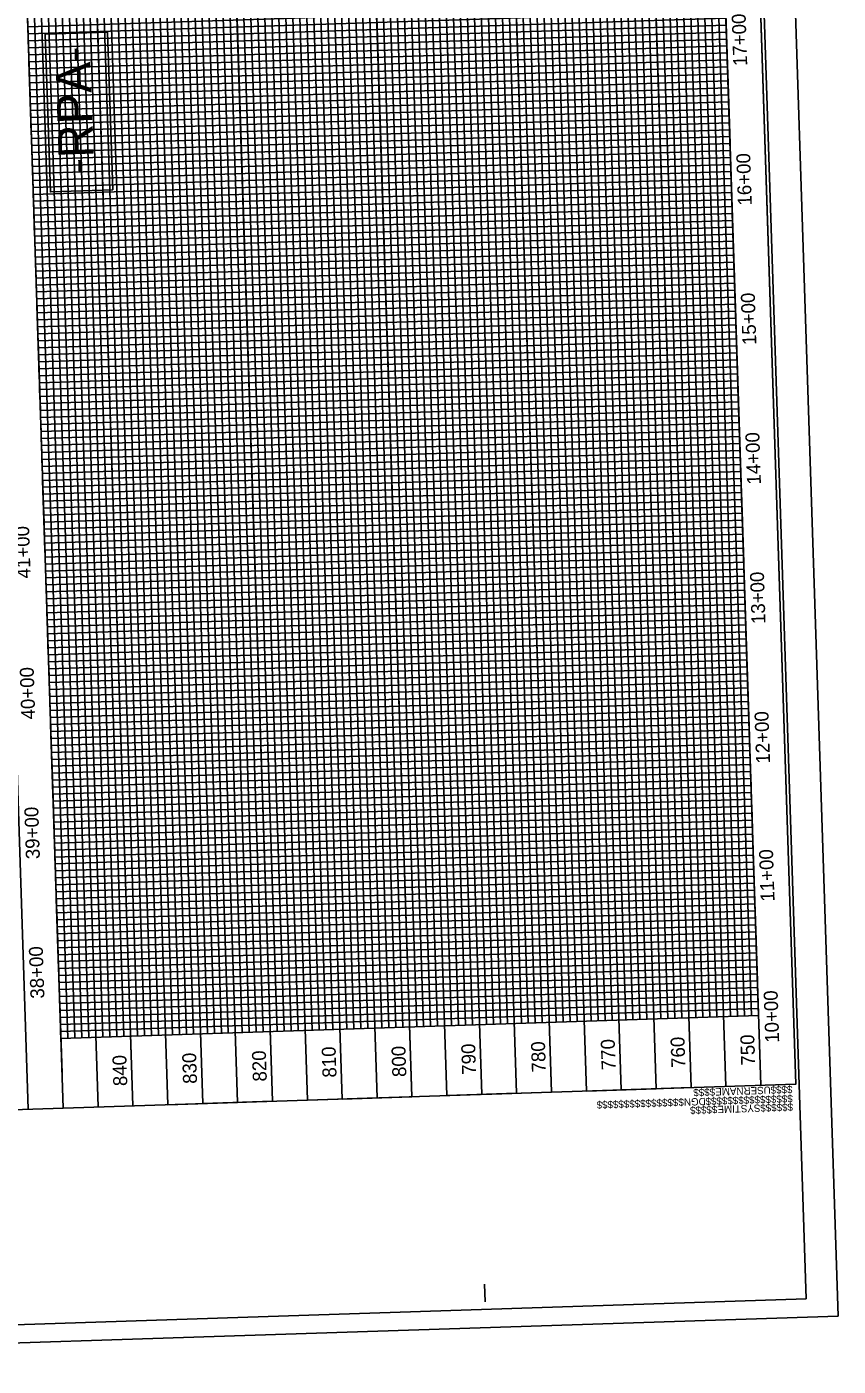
# Model space of a CAD drawing. Extents: x 1627318 to 1628473, y 762308 to 764226.
# Drawn here: x 1627891 to 1628473, y 762308 to 763268 of the extents above; entities that cross this region are included whole.
import ezdxf

# ---------------------------------------------------------------- set-up
doc = ezdxf.new("R2010")
doc.units = 0
for name, color, linetype in [('Exist Vertical Profile Horizontal Axis Label Major', 7, 'Continuous'), ('Exist Vertical Profile Vertical Axis Label', 7, 'Continuous'), ('Prop Grid Mask', 7, 'Continuous'), ('Sheet Data Field CELL', 7, 'Continuous'), ('Sheet DOT Grid CELL', 7, 'Continuous'), ('Sheet Layout Profile Border Port 2', 7, 'Continuous'), ('Sheet Plot Border Inside CELL', 7, 'Continuous'), ('Sheet Plot Border Outside CELL', 7, 'Continuous'), ('Sheet Profile CELL', 7, 'Continuous'), ('Sheet Profile Grid Major CELL', 7, 'Continuous'), ('Sheet Profile Grid Middle CELL', 7, 'Continuous'), ('Sheet Profile Grid Minor CELL', 7, 'Continuous')]:
    doc.layers.add(name, color=color, linetype=linetype)

msp = doc.modelspace()

# ---------------------------------------------------------------- linework, layer by layer
at = {"layer": 'Prop Grid Mask'}
msp.add_lwpolyline([(1627952.93, 763151.16), (1627949.24, 763264.18), (1627904.52, 763262.72), (1627908.21, 763149.69)], close=True, dxfattribs=at)
at = {"layer": 'Sheet DOT Grid CELL'}
for p, q in [((1628167.24, 762501.5), (1628118.21, 764000.59)), ((1628217.22, 762503.14), (1628168.18, 764002.22)), ((1628267.19, 762504.77), (1628218.15, 764003.86)), ((1628317.16, 762506.41), (1628268.13, 764005.49)), ((1628367.14, 762508.04), (1628318.1, 764007.13)), ((1627917.38, 762493.33), (1627868.34, 763992.41)), ((1627967.35, 762494.96), (1627918.31, 763994.05)), ((1628017.32, 762496.6), (1627968.29, 763995.68)), ((1628067.3, 762498.23), (1628018.26, 763997.32)), ((1628117.27, 762499.87), (1628068.23, 763998.95)), ((1627892.86, 763242.93), (1628392.59, 763259.27)), ((1627894.49, 763192.95), (1628394.22, 763209.3)), ((1627896.13, 763142.98), (1628395.86, 763159.33)), ((1627897.76, 763093.01), (1628397.49, 763109.35)), ((1627899.4, 763043.04), (1628399.13, 763059.38)), ((1627901.03, 762993.06), (1628400.76, 763009.41)), ((1627902.66, 762943.09), (1628402.4, 762959.43)), ((1627904.3, 762893.12), (1628404.03, 762909.46)), ((1627905.93, 762843.14), (1628405.67, 762859.49)), ((1627907.57, 762793.17), (1628407.3, 762809.51)), ((1627909.2, 762743.2), (1628408.94, 762759.54)), ((1627910.84, 762693.22), (1628410.57, 762709.57)), ((1627912.47, 762643.25), (1628412.21, 762659.6)), ((1627914.11, 762593.28), (1628413.84, 762609.62)), ((1627915.74, 762543.3), (1628415.47, 762559.65))]:
    msp.add_line(p, q, dxfattribs=at)
at = {"layer": 'Sheet Layout Profile Border Port 2'}
msp.add_lwpolyline([(1627915.74, 762543.3), (1627869.97, 763942.55), (1628369.71, 763958.9), (1628415.47, 762559.65)], close=True, dxfattribs=at)
at = {"layer": 'Sheet Plot Border Inside CELL'}
msp.add_lwpolyline([(1628449.68, 762356.66), (1628395.2, 764022.27), (1627340.66, 763987.77), (1627395.14, 762322.16)], close=True, dxfattribs=at)
at = {"layer": 'Sheet Plot Border Outside CELL'}
msp.add_lwpolyline([(1628472.54, 762344.4), (1628416.96, 764043.49), (1627317.55, 764007.53), (1627373.13, 762308.44)], close=True, dxfattribs=at)
at = {"layer": 'Sheet Profile CELL'}
for p, q in [((1628442.1, 762510.49), (1628393.06, 764009.69)), ((1628368.07, 764008.87), (1628417.11, 762509.68)), ((1627892.39, 762492.51), (1627843.35, 763991.71)), ((1627917.38, 762493.33), (1627868.34, 763992.53)), ((1628442.1, 762510.49), (1628442.1, 762510.49)), ((1628442.1, 762510.49), (1628442.1, 762510.49)), ((1628442.1, 762510.49), (1628442.1, 762510.49)), ((1628442.1, 762510.49), (1628442.1, 762510.49)), ((1628442.1, 762510.49), (1628442.1, 762510.49)), ((1628442.1, 762510.49), (1628442.1, 762510.49)), ((1628442.1, 762510.49), (1628442.1, 762510.49)), ((1628219.57, 762354.63), (1628219.16, 762367.13))]:
    msp.add_line(p, q, dxfattribs=at)
msp.add_lwpolyline([(1627343.62, 763975.36), (1627392.66, 762476.17), (1628442.1, 762510.49), (1628393.06, 764009.69)], close=True, dxfattribs=at)
msp.add_lwpolyline([(1628440.87, 762547.97), (1628440.87, 762547.97)], dxfattribs=at)
at = {"layer": 'Sheet Profile Grid Major CELL'}
for p, q in [((1627894.49, 763192.95), (1627892.86, 763242.93)), ((1627897.76, 763093.01), (1627896.13, 763142.98)), ((1627901.03, 762993.06), (1627899.4, 763043.04)), ((1628417.11, 762509.68), (1628417.11, 762509.68))]:
    msp.add_line(p, q, dxfattribs=at)
for points in [[(1628068.23, 763999.07), (1628117.27, 762499.87), (1628167.24, 762501.5), (1628118.2, 764000.7)], [(1628168.18, 764002.33), (1628217.22, 762503.14), (1628267.19, 762504.77), (1628218.15, 764003.97)], [(1628268.12, 764005.6), (1628317.16, 762506.41), (1628317.16, 762506.41), (1628367.14, 762508.04), (1628318.1, 764007.24)], [(1628368.07, 764008.87), (1628417.11, 762509.68)], [(1627918.31, 763994.16), (1627967.35, 762494.96)], [(1627968.28, 763995.8), (1628017.32, 762496.6), (1628067.3, 762498.23), (1628018.26, 763997.43)], [(1627915.74, 762543.3), (1628415.47, 762559.65), (1628413.84, 762609.62), (1627914.11, 762593.28), (1627912.47, 762643.25), (1628412.21, 762659.6), (1628410.57, 762709.57), (1627910.84, 762693.22), (1627909.2, 762743.2), (1628408.94, 762759.54), (1628407.3, 762809.51), (1627907.57, 762793.17), (1627905.93, 762843.14), (1628405.67, 762859.49), (1628404.03, 762909.46), (1627904.3, 762893.12), (1627902.66, 762943.09), (1628402.4, 762959.43), (1628400.76, 763009.41), (1627901.03, 762993.06), (1627899.4, 763043.04), (1628399.13, 763059.38), (1628397.49, 763109.35), (1627897.76, 763093.01), (1627896.13, 763142.98), (1628395.86, 763159.33), (1628394.22, 763209.3), (1627894.49, 763192.95), (1627892.86, 763242.93), (1628392.59, 763259.27), (1628390.96, 763309.25)]]:
    msp.add_lwpolyline(points, dxfattribs=at)
at = {"layer": 'Sheet Profile Grid Middle CELL'}
for points in [[(1628043.24, 763998.25), (1628092.28, 762499.05), (1628142.26, 762500.68), (1628093.22, 763999.88)], [(1628143.19, 764001.52), (1628192.23, 762502.32), (1628242.2, 762503.95), (1628193.16, 764003.15)], [(1628243.14, 764004.79), (1628292.18, 762505.59), (1628342.15, 762507.22), (1628293.11, 764006.42)], [(1628343.08, 764008.06), (1628392.12, 762508.86)], [(1627942.36, 762494.15), (1627893.32, 763993.34)], [(1627943.3, 763994.98), (1627992.34, 762495.78), (1628042.31, 762497.42), (1627993.27, 763996.61)], [(1627916.56, 762518.32), (1627914.92, 762568.29), (1628414.66, 762584.64), (1628413.02, 762634.61), (1627913.29, 762618.26), (1627911.66, 762668.24), (1628411.39, 762684.58), (1628409.75, 762734.55), (1627910.02, 762718.21), (1627908.39, 762768.18), (1628408.12, 762784.53), (1628406.48, 762834.5), (1627906.75, 762818.16), (1627905.12, 762868.13), (1628404.85, 762884.47), (1628403.21, 762934.45), (1627903.48, 762918.1), (1627901.85, 762968.08), (1628401.58, 762984.42), (1628399.95, 763034.39), (1627900.21, 763018.05), (1627898.58, 763068.02), (1628398.31, 763084.37), (1628396.68, 763134.34), (1628396.68, 763134.34), (1627896.94, 763117.99), (1627895.31, 763167.97), (1628395.04, 763184.31), (1628393.41, 763234.29), (1627893.67, 763217.94), (1627892.04, 763267.91), (1628391.77, 763284.26)]]:
    msp.add_lwpolyline(points, dxfattribs=at)
at = {"layer": 'Sheet Profile Grid Minor CELL'}
for p, q in [((1628154.82, 763951.87), (1628200.59, 762552.62)), ((1628205.59, 762552.78), (1628159.82, 763952.03)), ((1628164.81, 763952.2), (1628210.58, 762552.95)), ((1628220.58, 762553.27), (1628174.81, 763952.53)), ((1628179.81, 763952.69), (1628225.58, 762553.44)), ((1628230.57, 762553.6), (1628184.8, 763952.85)), ((1628189.8, 763953.02), (1628235.57, 762553.76)), ((1628245.57, 762554.09), (1628199.8, 763953.34)), ((1628204.79, 763953.51), (1628250.56, 762554.25)), ((1628255.56, 762554.42), (1628209.79, 763953.67)), ((1628214.79, 763953.83), (1628260.56, 762554.58)), ((1628270.55, 762554.91), (1628224.78, 763954.16)), ((1628229.78, 763954.32), (1628275.55, 762555.07)), ((1628280.55, 762555.24), (1628234.78, 763954.49)), ((1628239.77, 763954.65), (1628285.54, 762555.4)), ((1628295.54, 762555.73), (1628249.77, 763954.98)), ((1628254.77, 763955.14), (1628300.54, 762555.89)), ((1628305.53, 762556.05), (1628259.76, 763955.3)), ((1628264.76, 763955.47), (1628310.53, 762556.22)), ((1628320.53, 762556.54), (1628274.76, 763955.79)), ((1628279.75, 763955.96), (1628325.52, 762556.71)), ((1628330.52, 762556.87), (1628284.75, 763956.12)), ((1628289.75, 763956.28), (1628335.52, 762557.03)), ((1628345.51, 762557.36), (1628299.74, 763956.61)), ((1628304.74, 763956.78), (1628350.51, 762557.52)), ((1628355.51, 762557.69), (1628309.74, 763956.94)), ((1628314.73, 763957.1), (1628360.5, 762557.85)), ((1628370.5, 762558.18), (1628324.73, 763957.43)), ((1628329.73, 763957.59), (1628375.5, 762558.34)), ((1628380.49, 762558.5), (1628334.72, 763957.76)), ((1628339.72, 763957.92), (1628385.49, 762558.67)), ((1628395.49, 762558.99), (1628349.72, 763958.25)), ((1628354.71, 763958.41), (1628400.48, 762559.16)), ((1628405.48, 762559.32), (1628359.71, 763958.57)), ((1628410.48, 762559.49), (1628364.71, 763958.74)), ((1627920.74, 762543.47), (1627874.97, 763942.72)), ((1627879.97, 763942.88), (1627925.74, 762543.63)), ((1627930.73, 762543.79), (1627884.96, 763943.04)), ((1627889.96, 763943.21), (1627935.73, 762543.96)), ((1627945.73, 762544.28), (1627899.96, 763943.53)), ((1627904.95, 763943.7), (1627950.72, 762544.45)), ((1627955.72, 762544.61), (1627909.95, 763943.86)), ((1627914.95, 763944.03), (1627960.72, 762544.77)), ((1627970.71, 762545.1), (1627924.94, 763944.35)), ((1627929.94, 763944.52), (1627975.71, 762545.26)), ((1627980.71, 762545.43), (1627934.94, 763944.68)), ((1627939.94, 763944.84), (1627985.7, 762545.59)), ((1627995.7, 762545.92), (1627949.93, 763945.17)), ((1627954.93, 763945.33), (1628000.7, 762546.08)), ((1628005.69, 762546.24), (1627959.92, 763945.5)), ((1627964.92, 763945.66), (1628010.69, 762546.41)), ((1628020.69, 762546.74), (1627974.92, 763945.99)), ((1627979.91, 763946.15), (1628025.68, 762546.9)), ((1628030.68, 762547.06), (1627984.91, 763946.31)), ((1627989.91, 763946.48), (1628035.68, 762547.23)), ((1628045.67, 762547.55), (1627999.9, 763946.8)), ((1628004.9, 763946.97), (1628050.67, 762547.72)), ((1628055.67, 762547.88), (1628009.9, 763947.13)), ((1628014.89, 763947.29), (1628060.66, 762548.04)), ((1628070.66, 762548.37), (1628024.89, 763947.62)), ((1628029.89, 763947.78), (1628075.66, 762548.53)), ((1628080.65, 762548.7), (1628034.88, 763947.95)), ((1628039.88, 763948.11), (1628085.65, 762548.86)), ((1628095.65, 762549.19), (1628049.88, 763948.44)), ((1628054.87, 763948.6), (1628100.64, 762549.35)), ((1628105.64, 762549.51), (1628059.87, 763948.77)), ((1628064.87, 763948.93), (1628110.49, 762549.67)), ((1628120.63, 762550), (1628074.86, 763949.26)), ((1628079.86, 763949.42), (1628125.63, 762550.17)), ((1628130.63, 762550.33), (1628084.86, 763949.58)), ((1628089.85, 763949.75), (1628135.62, 762550.49)), ((1628145.62, 762550.82), (1628099.85, 763950.07)), ((1628104.85, 763950.24), (1628150.62, 762550.99)), ((1628155.61, 762551.15), (1628109.84, 763950.4)), ((1628114.84, 763950.56), (1628160.61, 762551.31)), ((1628170.61, 762551.64), (1628124.84, 763950.89)), ((1628129.83, 763951.05), (1628175.6, 762551.8)), ((1628180.6, 762551.97), (1628134.83, 763951.22)), ((1628139.83, 763951.38), (1628185.6, 762552.13)), ((1628195.59, 762552.46), (1628149.82, 763951.71))]:
    msp.add_line(p, q, dxfattribs=at)
for points in [[(1628391.94, 763279.26), (1627892.2, 763262.92), (1627891.88, 763272.91)], [(1627898.41, 763073.02), (1628398.15, 763089.37), (1628397.98, 763094.36), (1627898.25, 763078.02), (1627898.09, 763083.01), (1628397.82, 763099.36), (1628397.66, 763104.36), (1627897.92, 763088.01), (1627897.6, 763098.01), (1628397.33, 763114.35), (1628397.17, 763119.35), (1627897.43, 763103), (1627897.27, 763108), (1628397, 763124.35), (1628396.84, 763129.34), (1627897.11, 763113), (1627896.78, 763122.99), (1628396.51, 763139.34), (1628396.35, 763144.34), (1627896.62, 763127.99), (1627896.45, 763132.99), (1628396.19, 763149.33), (1628396.02, 763154.33), (1627896.29, 763137.98), (1627895.96, 763147.98), (1628395.7, 763164.33), (1628395.53, 763169.32), (1627895.8, 763152.98), (1627895.64, 763157.97), (1628395.37, 763174.32), (1628395.21, 763179.32), (1627895.47, 763162.97), (1627895.15, 763172.97), (1628394.88, 763189.31), (1628394.71, 763194.31), (1627894.98, 763177.96), (1627894.82, 763182.96), (1628394.55, 763199.31), (1628394.39, 763204.3), (1627894.66, 763187.96), (1627894.33, 763197.95), (1628394.06, 763214.3), (1628394.06, 763214.3), (1628393.9, 763219.3), (1627894.16, 763202.95), (1627894, 763207.95), (1628393.73, 763224.29), (1628393.57, 763229.29), (1627893.84, 763212.94), (1627893.51, 763222.94), (1628393.24, 763239.29), (1628393.08, 763244.28), (1627893.35, 763227.94), (1627893.18, 763232.93), (1628392.92, 763249.28), (1628392.75, 763254.28), (1627893.02, 763237.93), (1627892.69, 763247.93), (1628392.43, 763264.27), (1628392.26, 763269.27), (1627892.53, 763252.92), (1627892.37, 763257.92), (1628392.1, 763274.27)], [(1628408.45, 762774.53), (1628408.28, 762779.53), (1627908.55, 762763.18), (1627908.22, 762773.18), (1628407.96, 762789.53), (1628407.79, 762794.52), (1627908.06, 762778.18), (1627907.9, 762783.17), (1628407.63, 762799.52), (1628407.46, 762804.52), (1627907.73, 762788.17), (1627907.41, 762798.17), (1628407.14, 762814.51), (1628406.97, 762819.51), (1627907.24, 762803.16), (1627907.08, 762808.16), (1628406.81, 762824.51), (1628406.65, 762829.5), (1627906.91, 762813.16), (1627906.59, 762823.15), (1628406.32, 762839.5), (1628406.16, 762844.5), (1627906.42, 762828.15), (1627906.26, 762833.15), (1628405.99, 762849.49), (1628405.83, 762854.49), (1627906.1, 762838.14), (1627905.77, 762848.14), (1628405.5, 762864.49), (1628405.34, 762869.48), (1627905.61, 762853.14), (1627905.44, 762858.13), (1628405.18, 762874.48), (1628405.01, 762879.48), (1627905.28, 762863.13), (1627904.95, 762873.13), (1628404.69, 762889.47), (1628404.52, 762894.47), (1627904.79, 762878.12), (1627904.63, 762883.12), (1628404.36, 762899.47), (1628404.2, 762904.46), (1627904.46, 762888.12), (1627904.14, 762898.11), (1628403.87, 762914.46), (1628403.71, 762919.46), (1627903.97, 762903.11), (1627903.81, 762908.11), (1628403.54, 762924.45), (1628403.38, 762929.45), (1627903.65, 762913.1), (1627903.32, 762923.1), (1628403.05, 762939.45), (1628402.89, 762944.44), (1627903.16, 762928.1), (1627902.99, 762933.09), (1628402.72, 762949.44), (1628402.56, 762954.44), (1627902.83, 762938.09), (1627902.5, 762948.09), (1628402.23, 762964.43), (1628402.07, 762969.43), (1627902.34, 762953.08), (1627902.17, 762958.08), (1628401.91, 762974.43), (1628401.74, 762979.42), (1627902.01, 762963.08), (1627901.68, 762973.07), (1628401.42, 762989.42), (1628401.25, 762994.42), (1627901.52, 762978.07), (1627901.36, 762983.07), (1628401.09, 762999.41), (1628400.93, 763004.41), (1627901.19, 762988.06), (1627900.87, 762998.06), (1628400.6, 763014.41), (1628400.44, 763019.4), (1627900.7, 763003.06), (1627900.54, 763008.05), (1628400.27, 763024.4), (1628400.11, 763029.4), (1627900.38, 763013.05), (1627900.05, 763023.05), (1628399.78, 763039.39), (1628399.62, 763044.39), (1627899.89, 763028.04), (1627899.72, 763033.04), (1628399.46, 763049.39), (1628399.29, 763054.38), (1627899.56, 763038.04), (1627899.23, 763048.03), (1628398.96, 763064.38), (1628398.8, 763069.38), (1627899.07, 763053.03), (1627898.91, 763058.03), (1628398.64, 763074.37), (1628398.47, 763079.37), (1627898.74, 763063.02), (1627898.41, 763073.02)], [(1627915.74, 762543.3), (1627915.58, 762548.3), (1628415.31, 762564.65), (1628415.15, 762569.64), (1627915.41, 762553.3), (1627915.25, 762558.29), (1628414.98, 762574.64), (1628414.82, 762579.64), (1627915.09, 762563.29), (1627914.76, 762573.29), (1628414.49, 762589.63), (1628414.33, 762594.63), (1627914.6, 762578.28), (1627914.43, 762583.28), (1628414.17, 762599.63), (1628414, 762604.62), (1628413.68, 762614.62), (1628413.51, 762619.62), (1627913.78, 762603.27), (1627913.62, 762608.27), (1628413.35, 762624.61), (1628413.19, 762629.61), (1627913.45, 762613.26), (1627913.13, 762623.26), (1628412.86, 762639.61), (1628412.7, 762644.6), (1627912.96, 762628.26), (1627912.8, 762633.25), (1628412.53, 762649.6), (1628412.37, 762654.6), (1627912.64, 762638.25), (1627912.31, 762648.25), (1628412.04, 762664.59), (1628411.88, 762669.59), (1627912.15, 762653.24), (1627911.98, 762658.24), (1628411.71, 762674.59), (1628411.55, 762679.58), (1627911.82, 762663.24), (1627911.49, 762673.23), (1628411.22, 762689.58), (1628411.06, 762694.58), (1627911.33, 762678.23), (1627911.16, 762683.23), (1628410.9, 762699.57), (1628410.73, 762704.57), (1627911, 762688.22), (1627910.67, 762698.22), (1628410.41, 762714.57), (1628410.24, 762719.56), (1627910.51, 762703.22), (1627910.35, 762708.21), (1628410.08, 762724.56), (1628409.92, 762729.56), (1627910.18, 762713.21), (1627909.86, 762723.21), (1628409.59, 762739.55), (1628409.43, 762744.55), (1627909.69, 762728.2), (1627909.53, 762733.2), (1628409.26, 762749.55), (1628409.1, 762754.54), (1627909.37, 762738.2), (1627909.04, 762748.19), (1628408.77, 762764.54), (1628408.61, 762769.54), (1627908.88, 762753.19), (1627908.71, 762758.19), (1628408.45, 762774.53)], [(1628414, 762604.62), (1627914.27, 762588.28), (1627913.94, 762598.27), (1628413.68, 762614.62)]]:
    msp.add_lwpolyline(points, dxfattribs=at)

# ---------------------------------------------------------------- texts
at = {"layer": 'Exist Vertical Profile Horizontal Axis Label Major'}
for s, p in [('17+00', (1628407.42, 763240.05)), ('16+00', (1628410.69, 763140.1)), ('15+00', (1628413.96, 763040.15)), ('14+00', (1628417.23, 762940.21)), ('41+00', (1627894.15, 762872.96)), ('13+00', (1628420.5, 762840.26)), ('40+00', (1627897.45, 762771.93)), ('12+00', (1628423.77, 762740.31)), ('39+00', (1627900.73, 762671.86)), ('11+00', (1628427, 762641.45)), ('38+00', (1627903.99, 762571.92)), ('10+00', (1628430.31, 762540.3))]:
    msp.add_text(s, height=10, rotation=91.87347, dxfattribs=at).set_placement(p)
at = {"layer": 'Exist Vertical Profile Vertical Axis Label'}
for s, p in [('770', (1628313.14, 762520.7)), ('760', (1628363.11, 762522.33)), ('750', (1628413.08, 762523.97)), ('830', (1628013.3, 762510.89)), ('820', (1628063.27, 762512.53)), ('810', (1628113.21, 762515.36)), ('800', (1628163.22, 762515.79)), ('790', (1628213.19, 762517.43)), ('780', (1628263.16, 762519.06)), ('840', (1627963.33, 762509.26))]:
    msp.add_text(s, height=10, rotation=91.87347, dxfattribs=at).set_placement(p)
at = {"layer": 'Sheet Data Field CELL'}
msp.add_text('-RPA-', height=25, rotation=91.87347, dxfattribs=at).set_placement((1627939.48, 763163.32))
at = {"layer": 'Sheet Profile CELL'}
for s, p in [('$$$$$$$$$$$$$$$$DGN$$$$$$$$$$$$$$$$', (1628439.97, 762502.78)), ('$$$$USERNAME$$$$', (1628439.74, 762509.35)), ('$$$$$$SYSTIME$$$$$', (1628440.17, 762496.73))]:
    msp.add_text(s, height=5.25, rotation=181.87347, dxfattribs=at).set_placement(p)

doc.saveas('drawing.dxf')
